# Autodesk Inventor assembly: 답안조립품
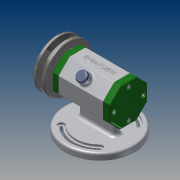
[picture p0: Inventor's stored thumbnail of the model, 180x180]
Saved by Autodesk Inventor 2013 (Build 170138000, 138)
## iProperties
Created: 2017-06
Part Number: 답안조립품
Document SubType Name: Assembly
Designer: Administrator
Author: Administrator
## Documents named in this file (14)
- C:\Users\Administrator\Desktop\470608V1018\답안조립품.iam
- C:\Users\Administrator\Desktop\470608V1018\본체.ipt
- C:\Users\Administrator\Desktop\470608V1018\뒤커버.ipt
- C:\Users\Administrator\Desktop\470608V1018\베어링 15 x 32 x 9.ipt
- C:\Users\Administrator\Desktop\470608V1018\볼트 M4 x 12.ipt
- C:\Users\Administrator\Desktop\470608V1018\축.ipt
- C:\Users\Administrator\Desktop\470608V1018\앞커버.ipt
- C:\Users\Administrator\Desktop\470608V1018\오일 실 15 25 7.ipt
- C:\Users\Administrator\Desktop\470608V1018\키 3 x 3 x 12.ipt
- C:\Users\Administrator\Desktop\470608V1018\V벨트풀리.ipt
- C:\Users\Administrator\Desktop\470608V1018\와셔 8x17.ipt
- C:\Users\Administrator\Desktop\470608V1018\스프링와셔 8.ipt
- C:\Users\Administrator\Desktop\470608V1018\너트 M 8.ipt
- C:\Users\Administrator\Desktop\470608V1018\고무캡.ipt
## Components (2 placed, 2 different names)
1. V벨트풀리:1 — 각도:3
2. 고무캡:1 — 각도:7
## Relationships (2: Angle 2)
- 각도:3 [Angle]: V벨트풀리:1
- 각도:7 [Angle]: 고무캡:1
